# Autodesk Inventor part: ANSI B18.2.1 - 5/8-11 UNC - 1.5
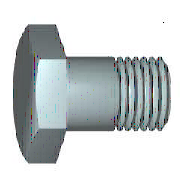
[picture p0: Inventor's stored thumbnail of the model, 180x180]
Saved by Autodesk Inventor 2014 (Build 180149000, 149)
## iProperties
Created: 2008-02
Part Number: ANSI B18.2.1 - 5/8-11 UNC - 1.5
Material: Steel, Mild
Description: Hex Cap Screw
Document SubType Name: Modeling
Standard: ANSI B18.2.1
Designer: floress
Standard Revision: 1996
Standards Organization: ANSI
Language: en-US
Size Designation: 5/8-11 UNC - 1.5
Categories: <MemberInstance><Categories><Category DisplayName="Fasteners" InternalName="e4da775c-781d-43d5-af7c-5136215cf5a6" Mnemonic="FSTN"><Category DisplayName="Bolts"
Density: 7.86 g/cm^3
Mass: 96.5696 g
Surface Area: 36.0161 cm^2
Volume: 12.2862 cm^3
Appearance: Steel
IsCustomPart: 0
Author: floress
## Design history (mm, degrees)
sketch "Sketch1"
  geometry: L1 (0, 10.716)-(0, 7.937); L2 (5.773, 7.937)-(38.1, 7.938); L3 (38.1, 7.938)-(38.1, 0); L4 (38.1, 0)-(-0.635, 0); L5 (-8.382, 0)-(45.847, 0) reference; L6 (-0.635, 0)-(-0.635, 10.716); L7 (-0.635, 10.716)-(0, 10.716); L8 (5.773, 7.937)-(0.002, 7.937); L9 (0.002, 7.937)-(0, 7.937); L10 (0, -2.143)-(0, 12.859) reference
  constraints: 16 end point, 2 collinear, 2 perpendicular, 1 parallel
  dimensions: "d0" = 38.1 distance between parallel lines of L3 L1 (= NLG); "d1" = 32.32734 distance from line of L2.start L3 (= GEL); "d2" = 15.875 diameter of L2 L4 (= GD); "d9" = 0.6351 distance between parallel lines of L6 L1 (computed from SD); "d10" = 21.43125 diameter of L7 L4 (= SD2); "d13" = 5.77022 distance of L2.start L8.end (computed from GAL); "d14" = 15.875 diameter of L9 L4 (= BDM)
revolve "Body" sketch "Sketch1" stored, may be unused: angle "d12" = 90 deg
sketch "Sketch2"
  geometry: L1 (0, 13.748)-(11.906, 6.874); L2 (11.906, 6.874)-(11.906, -6.874); L3 (11.906, -6.874)-(0, -13.748); L4 (0, -13.748)-(-11.906, -6.874); L5 (-11.906, -6.874)-(-11.906, 6.874); L6 (-11.906, 6.874)-(0, 13.748); 2 further points
  constraints: 12 end point, 1 coincident, 1 vertical, 11 other
  dimensions: "d11" = 23.8125 distance between parallel lines of L5 L2 (= SW)
extrude "Head" join sketch "Sketch2" distance "d3" = 9.28688 (= KOH - SD); taper "d4" = 0 deg
sketch "Sketch4"
  geometry: L1 (-9.922, 11.906)-(-9.922, 13.748); L2 (-9.922, 13.748)-(-8.859, 13.748); L3 (-8.859, 13.748)-(-9.922, 11.906); L4 (-11.779, 0)-(1.222, 0) reference; L5 (-0.635, 13.748)-(-9.922, 13.748) reference; L6 (-9.922, 6.874)-(-9.922, 13.748) reference
  constraints: 6 end point, 2 collinear, 1 perpendicular, 1 vertical
  dimensions: "d5" = 30 deg angle of L3 L1 (= ANG1); "d19" = 23.8125 diameter of L1.start L4 (= SW0)
revolve "Chamfer1" sketch "Sketch4" stored, may be unused: angle "d21" = 90 deg
workplane "Work Plane1"
fillet "Fillet2" dims "d63" = 1.143 (= R)
body "Solid1"
feature "Thread" dims "d15" = 32.32734 (= GEL), "d16" = 0
chamfer "Chamfer2" distance "d6" = 1.37414 (= -0.5 x SPD + 0.5 x GD); stored, may be unused: second distance "d7" = 1.37424 (computed from GUL), angle "d55" = 45 deg
other parameters: "NLG" = 38.1 [user parameter; used in 2 equation terms], "GD" = 15.875 (= NND) [user parameter; used in 2 equation terms], "BDM" = 15.875 [user parameter; used in 1 equation term], "KOH" = 9.92188 [user parameter; used in 1 equation term], "GEL" = 32.32734 [user parameter; used in 2 equation terms], "SW" = 23.8125 [user parameter; used in 3 equation terms], "SW0" = 23.8125 (= SW) [user parameter; used in 1 equation term], "SPD" = 13.12672 (= GD1) [user parameter; used in 1 equation term], "SD2" = 21.43125 [user parameter; used in 1 equation term], "SD" = 0.635 [user parameter; used in 3 equation terms], "ANG1" = 30 deg [user parameter; used in 1 equation term], "GAL" = 5.77012 [user parameter; used in 1 equation term], "GUL" = 1.37414 [user parameter; used in 2 equation terms], "d8" = 0, "R" = 1.143 [user parameter; used in 1 equation term], "d58" = 0, "d62" = -37.36086 (= -NLG - SD + GUL), "THREADDIA" = 15.875 [user parameter], "TOA" = 30 deg [user parameter], "RR" = 1.524 [user parameter], "PTC" = 2.30909 (computed from TPU) [user parameter], "NND" = 15.875 [user parameter; used in 1 equation term], "E0" = 27.50344 (= 1.155 x SW) [user parameter], "SLG" = 0 [user parameter], "GD1" = 13.12672 [user parameter; used in 1 equation term]
